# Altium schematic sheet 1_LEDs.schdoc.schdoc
size 309 x 223 mm; Symbol: Sheet-Symbol_A4; Device: Sheet-Symbol_A4; @Project Name: LuxBadge2024; @Page Count: 2; @Update Date: 2024-06-25; @Create Date: 2024-06-16; @Schematic Name: Schematic1; @Page No: 2; @Page Name: LEDs; Company: EasyEDA.com; Reviewed: EasyEDA; Version: V0.1; Page Size: A4; Part Number: JLCPCB-002; Drawn: EasyEDA
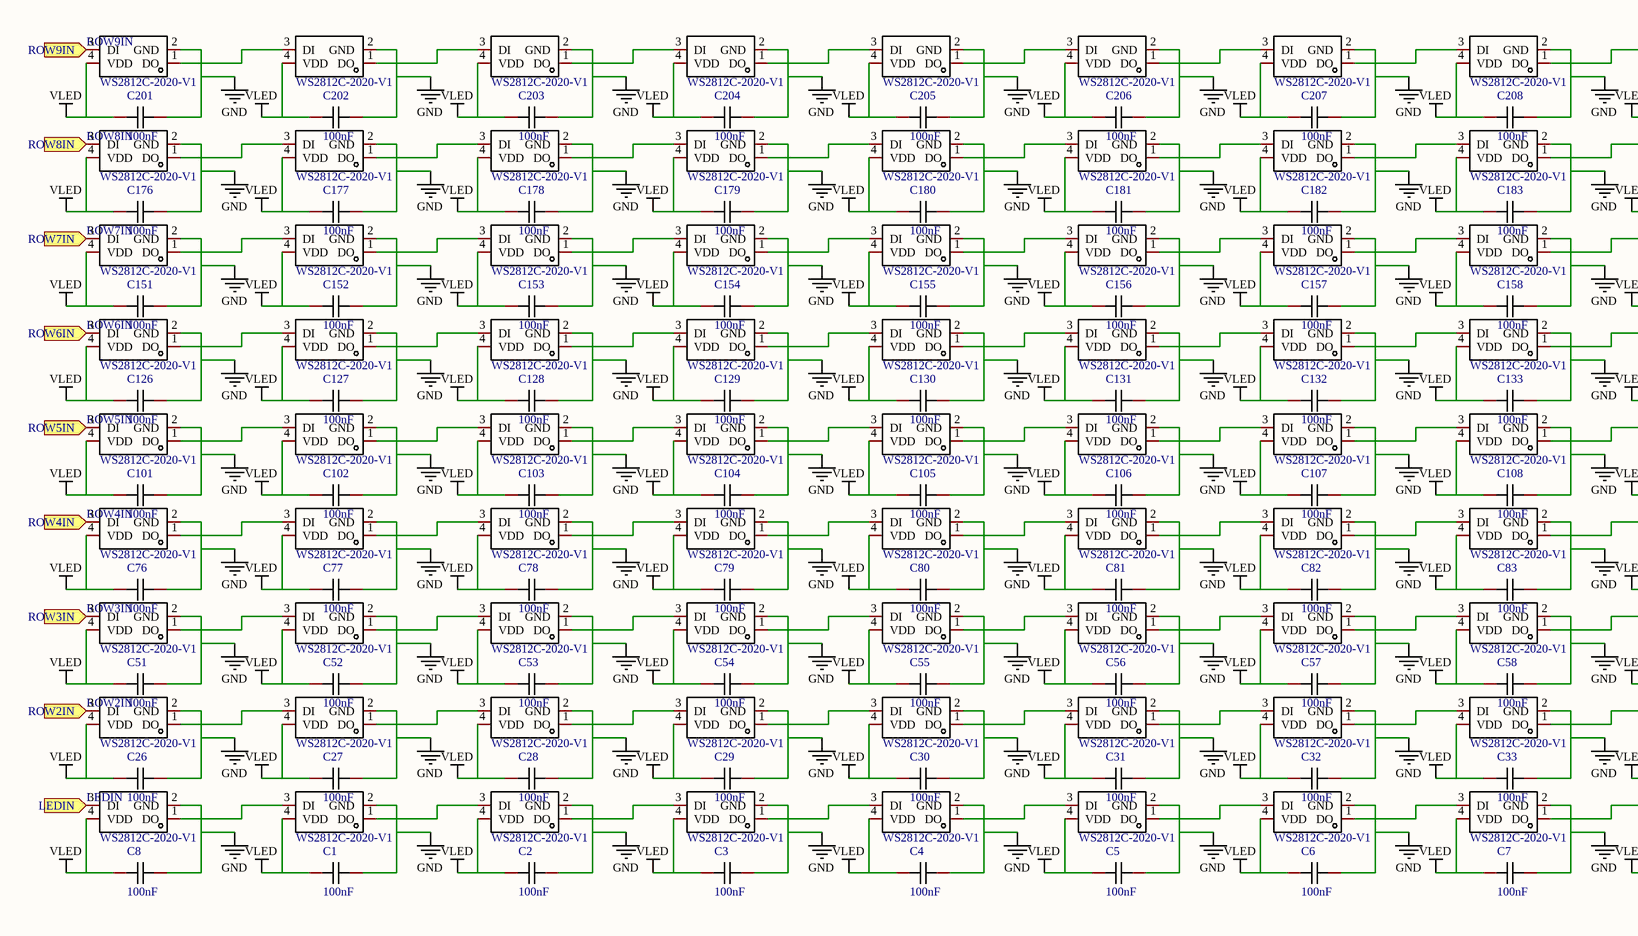
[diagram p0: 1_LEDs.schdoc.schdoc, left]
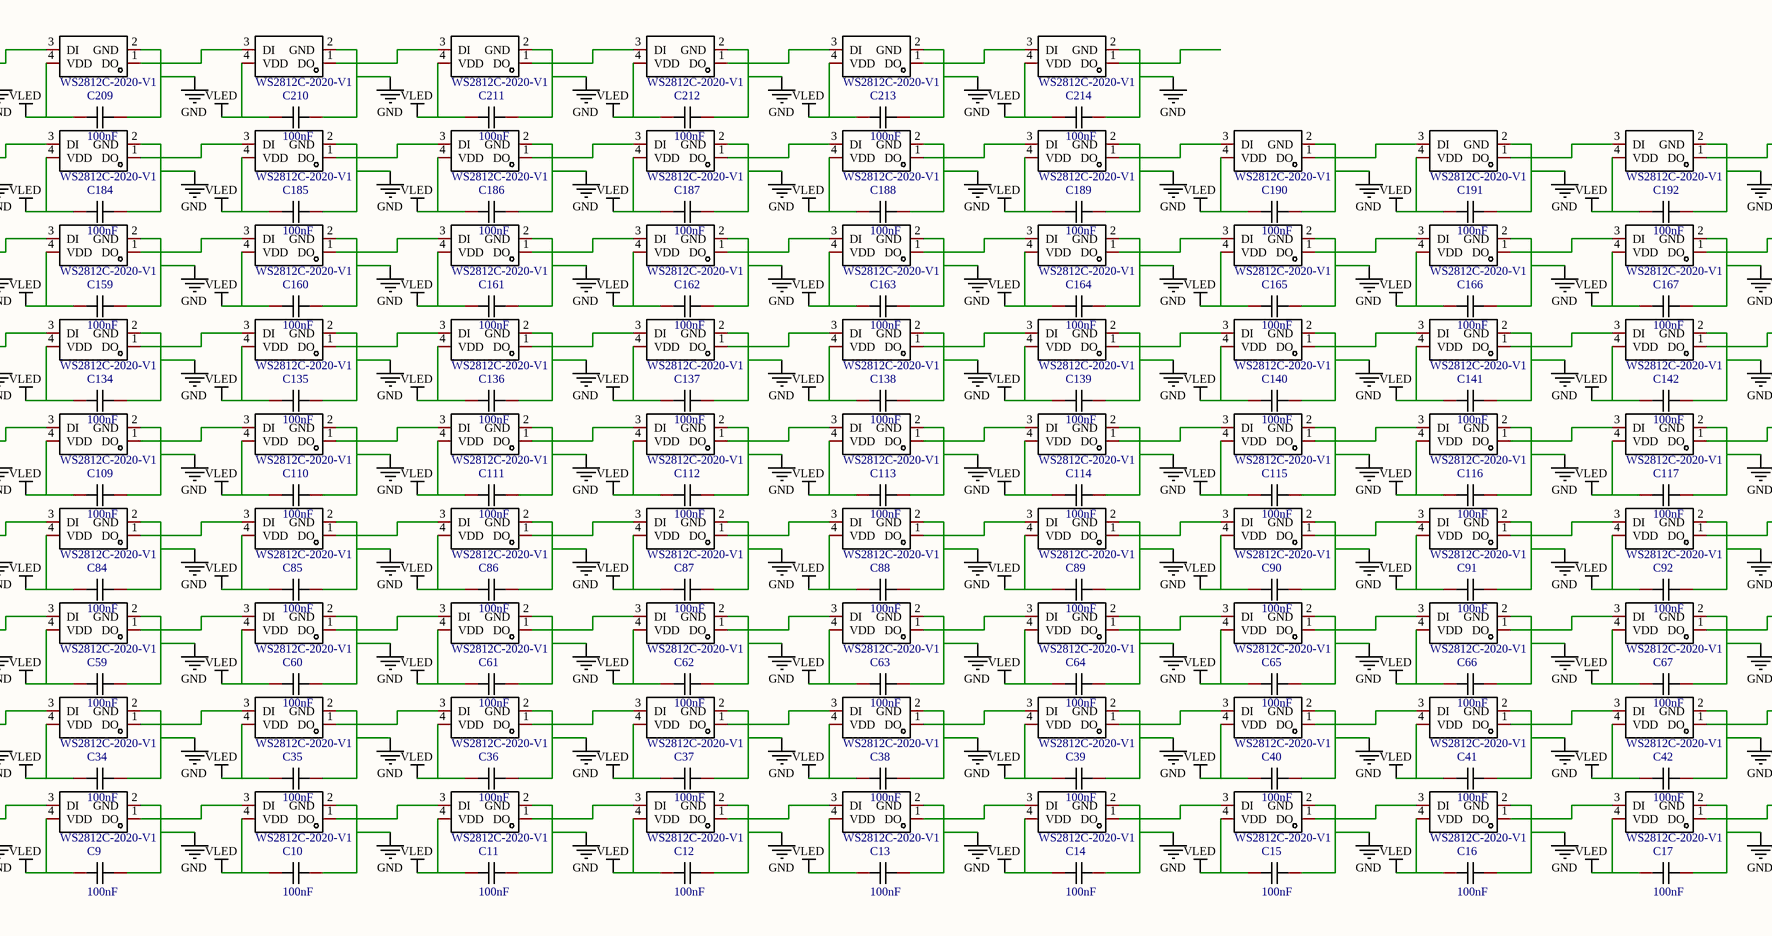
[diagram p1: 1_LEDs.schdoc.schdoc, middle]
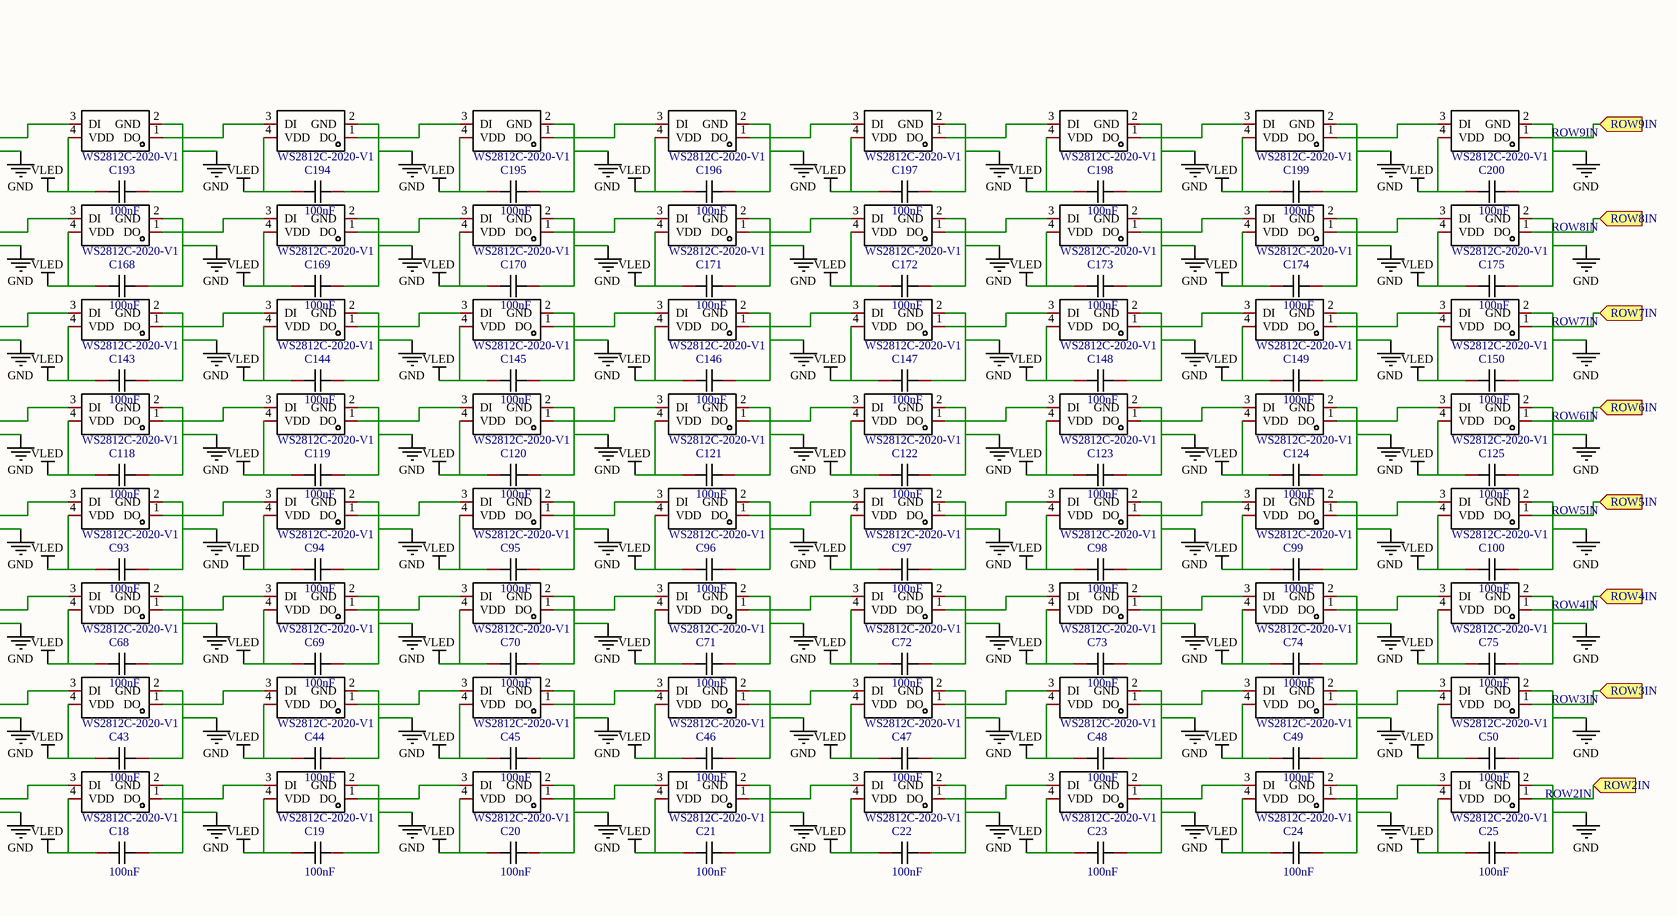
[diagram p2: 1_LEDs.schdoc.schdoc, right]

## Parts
C1  100nF  [C0402]
C2  100nF  [C0402]
C3  100nF  [C0402]
C4  100nF  [C0402]
C5  100nF  [C0402]
C6  100nF  [C0402]
C7  100nF  [C0402]
C8  100nF  [C0402]
C9  100nF  [C0402]
C10  100nF  [C0402]
C11  100nF  [C0402]
C12  100nF  [C0402]
C13  100nF  [C0402]
C14  100nF  [C0402]
C15  100nF  [C0402]
C16  100nF  [C0402]
C17  100nF  [C0402]
C18  100nF  [C0402]
C19  100nF  [C0402]
C20  100nF  [C0402]
C21  100nF  [C0402]
C22  100nF  [C0402]
C23  100nF  [C0402]
C24  100nF  [C0402]
C25  100nF  [C0402]
C26  100nF  [C0402]
C27  100nF  [C0402]
C28  100nF  [C0402]
C29  100nF  [C0402]
C30  100nF  [C0402]
C31  100nF  [C0402]
C32  100nF  [C0402]
C33  100nF  [C0402]
C34  100nF  [C0402]
C35  100nF  [C0402]
C36  100nF  [C0402]
C37  100nF  [C0402]
C38  100nF  [C0402]
C39  100nF  [C0402]
C40  100nF  [C0402]
C41  100nF  [C0402]
C42  100nF  [C0402]
C43  100nF  [C0402]
C44  100nF  [C0402]
C45  100nF  [C0402]
C46  100nF  [C0402]
C47  100nF  [C0402]
C48  100nF  [C0402]
C49  100nF  [C0402]
C50  100nF  [C0402]
C51  100nF  [C0402]
C52  100nF  [C0402]
C53  100nF  [C0402]
C54  100nF  [C0402]
C55  100nF  [C0402]
C56  100nF  [C0402]
C57  100nF  [C0402]
C58  100nF  [C0402]
C59  100nF  [C0402]
C60  100nF  [C0402]
C61  100nF  [C0402]
C62  100nF  [C0402]
C63  100nF  [C0402]
C64  100nF  [C0402]
C65  100nF  [C0402]
C66  100nF  [C0402]
C67  100nF  [C0402]
C68  100nF  [C0402]
C69  100nF  [C0402]
C70  100nF  [C0402]
C71  100nF  [C0402]
C72  100nF  [C0402]
C73  100nF  [C0402]
C74  100nF  [C0402]
C75  100nF  [C0402]
C76  100nF  [C0402]
C77  100nF  [C0402]
C78  100nF  [C0402]
C79  100nF  [C0402]
C80  100nF  [C0402]
C81  100nF  [C0402]
C82  100nF  [C0402]
C83  100nF  [C0402]
C84  100nF  [C0402]
C85  100nF  [C0402]
C86  100nF  [C0402]
C87  100nF  [C0402]
C88  100nF  [C0402]
C89  100nF  [C0402]
C90  100nF  [C0402]
C91  100nF  [C0402]
C92  100nF  [C0402]
C93  100nF  [C0402]
C94  100nF  [C0402]
C95  100nF  [C0402]
C96  100nF  [C0402]
C97  100nF  [C0402]
C98  100nF  [C0402]
C99  100nF  [C0402]
C100  100nF  [C0402]
C101  100nF  [C0402]
C102  100nF  [C0402]
C103  100nF  [C0402]
C104  100nF  [C0402]
C105  100nF  [C0402]
C106  100nF  [C0402]
C107  100nF  [C0402]
C108  100nF  [C0402]
C109  100nF  [C0402]
C110  100nF  [C0402]
C111  100nF  [C0402]
C112  100nF  [C0402]
C113  100nF  [C0402]
C114  100nF  [C0402]
C115  100nF  [C0402]
C116  100nF  [C0402]
C117  100nF  [C0402]
C118  100nF  [C0402]
C119  100nF  [C0402]
C120  100nF  [C0402]
C121  100nF  [C0402]
C122  100nF  [C0402]
C123  100nF  [C0402]
C124  100nF  [C0402]
C125  100nF  [C0402]
C126  100nF  [C0402]
C127  100nF  [C0402]
C128  100nF  [C0402]
C129  100nF  [C0402]
C130  100nF  [C0402]
C131  100nF  [C0402]
C132  100nF  [C0402]
C133  100nF  [C0402]
C134  100nF  [C0402]
C135  100nF  [C0402]
C136  100nF  [C0402]
C137  100nF  [C0402]
C138  100nF  [C0402]
C139  100nF  [C0402]
C140  100nF  [C0402]
C141  100nF  [C0402]
C142  100nF  [C0402]
C143  100nF  [C0402]
C144  100nF  [C0402]
C145  100nF  [C0402]
C146  100nF  [C0402]
C147  100nF  [C0402]
C148  100nF  [C0402]
C149  100nF  [C0402]
C150  100nF  [C0402]
C151  100nF  [C0402]
C152  100nF  [C0402]
C153  100nF  [C0402]
C154  100nF  [C0402]
C155  100nF  [C0402]
C156  100nF  [C0402]
C157  100nF  [C0402]
C158  100nF  [C0402]
C159  100nF  [C0402]
C160  100nF  [C0402]
C161  100nF  [C0402]
C162  100nF  [C0402]
C163  100nF  [C0402]
C164  100nF  [C0402]
C165  100nF  [C0402]
C166  100nF  [C0402]
C167  100nF  [C0402]
C168  100nF  [C0402]
C169  100nF  [C0402]
C170  100nF  [C0402]
C171  100nF  [C0402]
C172  100nF  [C0402]
C173  100nF  [C0402]
C174  100nF  [C0402]
C175  100nF  [C0402]
C176  100nF  [C0402]
C177  100nF  [C0402]
C178  100nF  [C0402]
C179  100nF  [C0402]
C180  100nF  [C0402]
C181  100nF  [C0402]
C182  100nF  [C0402]
C183  100nF  [C0402]
C184  100nF  [C0402]
C185  100nF  [C0402]
C186  100nF  [C0402]
C187  100nF  [C0402]
C188  100nF  [C0402]
C189  100nF  [C0402]
C190  100nF  [C0402]
C191  100nF  [C0402]
C192  100nF  [C0402]
C193  100nF  [C0402]
C194  100nF  [C0402]
C195  100nF  [C0402]
C196  100nF  [C0402]
C197  100nF  [C0402]
C198  100nF  [C0402]
C199  100nF  [C0402]
C200  100nF  [C0402]
C201  100nF  [C0402]
C202  100nF  [C0402]
C203  100nF  [C0402]
C204  100nF  [C0402]
C205  100nF  [C0402]
C206  100nF  [C0402]
C207  100nF  [C0402]
C208  100nF  [C0402]
C209  100nF  [C0402]
C210  100nF  [C0402]
C211  100nF  [C0402]
C212  100nF  [C0402]
C213  100nF  [C0402]
C214  100nF  [C0402]
LED1  WS2812C-2020-V1  [LED-SMD_4P-L2.0-W2.0-TL_WS2812B-2020]
LED2  WS2812C-2020-V1  [LED-SMD_4P-L2.0-W2.0-TL_WS2812B-2020]
LED3  WS2812C-2020-V1  [LED-SMD_4P-L2.0-W2.0-TL_WS2812B-2020]
LED4  WS2812C-2020-V1  [LED-SMD_4P-L2.0-W2.0-TL_WS2812B-2020]
LED5  WS2812C-2020-V1  [LED-SMD_4P-L2.0-W2.0-TL_WS2812B-2020]
LED6  WS2812C-2020-V1  [LED-SMD_4P-L2.0-W2.0-TL_WS2812B-2020]
LED7  WS2812C-2020-V1  [LED-SMD_4P-L2.0-W2.0-TL_WS2812B-2020]
LED8  WS2812C-2020-V1  [LED-SMD_4P-L2.0-W2.0-TL_WS2812B-2020]
LED9  WS2812C-2020-V1  [LED-SMD_4P-L2.0-W2.0-TL_WS2812B-2020]
LED10  WS2812C-2020-V1  [LED-SMD_4P-L2.0-W2.0-TL_WS2812B-2020]
LED11  WS2812C-2020-V1  [LED-SMD_4P-L2.0-W2.0-TL_WS2812B-2020]
LED12  WS2812C-2020-V1  [LED-SMD_4P-L2.0-W2.0-TL_WS2812B-2020]
LED13  WS2812C-2020-V1  [LED-SMD_4P-L2.0-W2.0-TL_WS2812B-2020]
LED14  WS2812C-2020-V1  [LED-SMD_4P-L2.0-W2.0-TL_WS2812B-2020]
LED15  WS2812C-2020-V1  [LED-SMD_4P-L2.0-W2.0-TL_WS2812B-2020]
LED16  WS2812C-2020-V1  [LED-SMD_4P-L2.0-W2.0-TL_WS2812B-2020]
LED17  WS2812C-2020-V1  [LED-SMD_4P-L2.0-W2.0-TL_WS2812B-2020]
LED18  WS2812C-2020-V1  [LED-SMD_4P-L2.0-W2.0-TL_WS2812B-2020]
LED19  WS2812C-2020-V1  [LED-SMD_4P-L2.0-W2.0-TL_WS2812B-2020]
LED20  WS2812C-2020-V1  [LED-SMD_4P-L2.0-W2.0-TL_WS2812B-2020]
LED21  WS2812C-2020-V1  [LED-SMD_4P-L2.0-W2.0-TL_WS2812B-2020]
LED22  WS2812C-2020-V1  [LED-SMD_4P-L2.0-W2.0-TL_WS2812B-2020]
LED23  WS2812C-2020-V1  [LED-SMD_4P-L2.0-W2.0-TL_WS2812B-2020]
LED24  WS2812C-2020-V1  [LED-SMD_4P-L2.0-W2.0-TL_WS2812B-2020]
LED25  WS2812C-2020-V1  [LED-SMD_4P-L2.0-W2.0-TL_WS2812B-2020]
LED26  WS2812C-2020-V1  [LED-SMD_4P-L2.0-W2.0-TL_WS2812B-2020]
LED27  WS2812C-2020-V1  [LED-SMD_4P-L2.0-W2.0-TL_WS2812B-2020]
LED28  WS2812C-2020-V1  [LED-SMD_4P-L2.0-W2.0-TL_WS2812B-2020]
LED29  WS2812C-2020-V1  [LED-SMD_4P-L2.0-W2.0-TL_WS2812B-2020]
LED30  WS2812C-2020-V1  [LED-SMD_4P-L2.0-W2.0-TL_WS2812B-2020]
LED31  WS2812C-2020-V1  [LED-SMD_4P-L2.0-W2.0-TL_WS2812B-2020]
LED32  WS2812C-2020-V1  [LED-SMD_4P-L2.0-W2.0-TL_WS2812B-2020]
LED33  WS2812C-2020-V1  [LED-SMD_4P-L2.0-W2.0-TL_WS2812B-2020]
LED34  WS2812C-2020-V1  [LED-SMD_4P-L2.0-W2.0-TL_WS2812B-2020]
LED35  WS2812C-2020-V1  [LED-SMD_4P-L2.0-W2.0-TL_WS2812B-2020]
LED36  WS2812C-2020-V1  [LED-SMD_4P-L2.0-W2.0-TL_WS2812B-2020]
LED37  WS2812C-2020-V1  [LED-SMD_4P-L2.0-W2.0-TL_WS2812B-2020]
LED38  WS2812C-2020-V1  [LED-SMD_4P-L2.0-W2.0-TL_WS2812B-2020]
LED39  WS2812C-2020-V1  [LED-SMD_4P-L2.0-W2.0-TL_WS2812B-2020]
LED40  WS2812C-2020-V1  [LED-SMD_4P-L2.0-W2.0-TL_WS2812B-2020]
LED41  WS2812C-2020-V1  [LED-SMD_4P-L2.0-W2.0-TL_WS2812B-2020]
LED42  WS2812C-2020-V1  [LED-SMD_4P-L2.0-W2.0-TL_WS2812B-2020]
LED43  WS2812C-2020-V1  [LED-SMD_4P-L2.0-W2.0-TL_WS2812B-2020]
LED44  WS2812C-2020-V1  [LED-SMD_4P-L2.0-W2.0-TL_WS2812B-2020]
LED45  WS2812C-2020-V1  [LED-SMD_4P-L2.0-W2.0-TL_WS2812B-2020]
LED46  WS2812C-2020-V1  [LED-SMD_4P-L2.0-W2.0-TL_WS2812B-2020]
LED47  WS2812C-2020-V1  [LED-SMD_4P-L2.0-W2.0-TL_WS2812B-2020]
LED48  WS2812C-2020-V1  [LED-SMD_4P-L2.0-W2.0-TL_WS2812B-2020]
LED49  WS2812C-2020-V1  [LED-SMD_4P-L2.0-W2.0-TL_WS2812B-2020]
LED50  WS2812C-2020-V1  [LED-SMD_4P-L2.0-W2.0-TL_WS2812B-2020]
LED51  WS2812C-2020-V1  [LED-SMD_4P-L2.0-W2.0-TL_WS2812B-2020]
LED52  WS2812C-2020-V1  [LED-SMD_4P-L2.0-W2.0-TL_WS2812B-2020]
LED53  WS2812C-2020-V1  [LED-SMD_4P-L2.0-W2.0-TL_WS2812B-2020]
LED54  WS2812C-2020-V1  [LED-SMD_4P-L2.0-W2.0-TL_WS2812B-2020]
LED55  WS2812C-2020-V1  [LED-SMD_4P-L2.0-W2.0-TL_WS2812B-2020]
LED56  WS2812C-2020-V1  [LED-SMD_4P-L2.0-W2.0-TL_WS2812B-2020]
LED57  WS2812C-2020-V1  [LED-SMD_4P-L2.0-W2.0-TL_WS2812B-2020]
LED58  WS2812C-2020-V1  [LED-SMD_4P-L2.0-W2.0-TL_WS2812B-2020]
LED59  WS2812C-2020-V1  [LED-SMD_4P-L2.0-W2.0-TL_WS2812B-2020]
LED60  WS2812C-2020-V1  [LED-SMD_4P-L2.0-W2.0-TL_WS2812B-2020]
LED61  WS2812C-2020-V1  [LED-SMD_4P-L2.0-W2.0-TL_WS2812B-2020]
LED62  WS2812C-2020-V1  [LED-SMD_4P-L2.0-W2.0-TL_WS2812B-2020]
LED63  WS2812C-2020-V1  [LED-SMD_4P-L2.0-W2.0-TL_WS2812B-2020]
LED64  WS2812C-2020-V1  [LED-SMD_4P-L2.0-W2.0-TL_WS2812B-2020]
LED65  WS2812C-2020-V1  [LED-SMD_4P-L2.0-W2.0-TL_WS2812B-2020]
LED66  WS2812C-2020-V1  [LED-SMD_4P-L2.0-W2.0-TL_WS2812B-2020]
LED67  WS2812C-2020-V1  [LED-SMD_4P-L2.0-W2.0-TL_WS2812B-2020]
LED68  WS2812C-2020-V1  [LED-SMD_4P-L2.0-W2.0-TL_WS2812B-2020]
LED69  WS2812C-2020-V1  [LED-SMD_4P-L2.0-W2.0-TL_WS2812B-2020]
LED70  WS2812C-2020-V1  [LED-SMD_4P-L2.0-W2.0-TL_WS2812B-2020]
LED71  WS2812C-2020-V1  [LED-SMD_4P-L2.0-W2.0-TL_WS2812B-2020]
LED72  WS2812C-2020-V1  [LED-SMD_4P-L2.0-W2.0-TL_WS2812B-2020]
LED73  WS2812C-2020-V1  [LED-SMD_4P-L2.0-W2.0-TL_WS2812B-2020]
LED74  WS2812C-2020-V1  [LED-SMD_4P-L2.0-W2.0-TL_WS2812B-2020]
LED75  WS2812C-2020-V1  [LED-SMD_4P-L2.0-W2.0-TL_WS2812B-2020]
LED76  WS2812C-2020-V1  [LED-SMD_4P-L2.0-W2.0-TL_WS2812B-2020]
LED77  WS2812C-2020-V1  [LED-SMD_4P-L2.0-W2.0-TL_WS2812B-2020]
LED78  WS2812C-2020-V1  [LED-SMD_4P-L2.0-W2.0-TL_WS2812B-2020]
LED79  WS2812C-2020-V1  [LED-SMD_4P-L2.0-W2.0-TL_WS2812B-2020]
LED80  WS2812C-2020-V1  [LED-SMD_4P-L2.0-W2.0-TL_WS2812B-2020]
LED81  WS2812C-2020-V1  [LED-SMD_4P-L2.0-W2.0-TL_WS2812B-2020]
LED82  WS2812C-2020-V1  [LED-SMD_4P-L2.0-W2.0-TL_WS2812B-2020]
LED83  WS2812C-2020-V1  [LED-SMD_4P-L2.0-W2.0-TL_WS2812B-2020]
LED84  WS2812C-2020-V1  [LED-SMD_4P-L2.0-W2.0-TL_WS2812B-2020]
LED85  WS2812C-2020-V1  [LED-SMD_4P-L2.0-W2.0-TL_WS2812B-2020]
LED86  WS2812C-2020-V1  [LED-SMD_4P-L2.0-W2.0-TL_WS2812B-2020]
LED87  WS2812C-2020-V1  [LED-SMD_4P-L2.0-W2.0-TL_WS2812B-2020]
LED88  WS2812C-2020-V1  [LED-SMD_4P-L2.0-W2.0-TL_WS2812B-2020]
LED89  WS2812C-2020-V1  [LED-SMD_4P-L2.0-W2.0-TL_WS2812B-2020]
LED90  WS2812C-2020-V1  [LED-SMD_4P-L2.0-W2.0-TL_WS2812B-2020]
LED91  WS2812C-2020-V1  [LED-SMD_4P-L2.0-W2.0-TL_WS2812B-2020]
LED92  WS2812C-2020-V1  [LED-SMD_4P-L2.0-W2.0-TL_WS2812B-2020]
LED93  WS2812C-2020-V1  [LED-SMD_4P-L2.0-W2.0-TL_WS2812B-2020]
LED94  WS2812C-2020-V1  [LED-SMD_4P-L2.0-W2.0-TL_WS2812B-2020]
LED95  WS2812C-2020-V1  [LED-SMD_4P-L2.0-W2.0-TL_WS2812B-2020]
LED96  WS2812C-2020-V1  [LED-SMD_4P-L2.0-W2.0-TL_WS2812B-2020]
LED97  WS2812C-2020-V1  [LED-SMD_4P-L2.0-W2.0-TL_WS2812B-2020]
LED98  WS2812C-2020-V1  [LED-SMD_4P-L2.0-W2.0-TL_WS2812B-2020]
LED99  WS2812C-2020-V1  [LED-SMD_4P-L2.0-W2.0-TL_WS2812B-2020]
LED100  WS2812C-2020-V1  [LED-SMD_4P-L2.0-W2.0-TL_WS2812B-2020]
LED101  WS2812C-2020-V1  [LED-SMD_4P-L2.0-W2.0-TL_WS2812B-2020]
LED102  WS2812C-2020-V1  [LED-SMD_4P-L2.0-W2.0-TL_WS2812B-2020]
LED103  WS2812C-2020-V1  [LED-SMD_4P-L2.0-W2.0-TL_WS2812B-2020]
LED104  WS2812C-2020-V1  [LED-SMD_4P-L2.0-W2.0-TL_WS2812B-2020]
LED105  WS2812C-2020-V1  [LED-SMD_4P-L2.0-W2.0-TL_WS2812B-2020]
LED106  WS2812C-2020-V1  [LED-SMD_4P-L2.0-W2.0-TL_WS2812B-2020]
LED107  WS2812C-2020-V1  [LED-SMD_4P-L2.0-W2.0-TL_WS2812B-2020]
LED108  WS2812C-2020-V1  [LED-SMD_4P-L2.0-W2.0-TL_WS2812B-2020]
LED109  WS2812C-2020-V1  [LED-SMD_4P-L2.0-W2.0-TL_WS2812B-2020]
LED110  WS2812C-2020-V1  [LED-SMD_4P-L2.0-W2.0-TL_WS2812B-2020]
LED111  WS2812C-2020-V1  [LED-SMD_4P-L2.0-W2.0-TL_WS2812B-2020]
LED112  WS2812C-2020-V1  [LED-SMD_4P-L2.0-W2.0-TL_WS2812B-2020]
LED113  WS2812C-2020-V1  [LED-SMD_4P-L2.0-W2.0-TL_WS2812B-2020]
LED114  WS2812C-2020-V1  [LED-SMD_4P-L2.0-W2.0-TL_WS2812B-2020]
LED115  WS2812C-2020-V1  [LED-SMD_4P-L2.0-W2.0-TL_WS2812B-2020]
LED116  WS2812C-2020-V1  [LED-SMD_4P-L2.0-W2.0-TL_WS2812B-2020]
LED117  WS2812C-2020-V1  [LED-SMD_4P-L2.0-W2.0-TL_WS2812B-2020]
LED118  WS2812C-2020-V1  [LED-SMD_4P-L2.0-W2.0-TL_WS2812B-2020]
LED119  WS2812C-2020-V1  [LED-SMD_4P-L2.0-W2.0-TL_WS2812B-2020]
LED120  WS2812C-2020-V1  [LED-SMD_4P-L2.0-W2.0-TL_WS2812B-2020]
LED121  WS2812C-2020-V1  [LED-SMD_4P-L2.0-W2.0-TL_WS2812B-2020]
LED122  WS2812C-2020-V1  [LED-SMD_4P-L2.0-W2.0-TL_WS2812B-2020]
LED123  WS2812C-2020-V1  [LED-SMD_4P-L2.0-W2.0-TL_WS2812B-2020]
LED124  WS2812C-2020-V1  [LED-SMD_4P-L2.0-W2.0-TL_WS2812B-2020]
LED125  WS2812C-2020-V1  [LED-SMD_4P-L2.0-W2.0-TL_WS2812B-2020]
LED126  WS2812C-2020-V1  [LED-SMD_4P-L2.0-W2.0-TL_WS2812B-2020]
LED127  WS2812C-2020-V1  [LED-SMD_4P-L2.0-W2.0-TL_WS2812B-2020]
LED128  WS2812C-2020-V1  [LED-SMD_4P-L2.0-W2.0-TL_WS2812B-2020]
LED129  WS2812C-2020-V1  [LED-SMD_4P-L2.0-W2.0-TL_WS2812B-2020]
LED130  WS2812C-2020-V1  [LED-SMD_4P-L2.0-W2.0-TL_WS2812B-2020]
LED131  WS2812C-2020-V1  [LED-SMD_4P-L2.0-W2.0-TL_WS2812B-2020]
LED132  WS2812C-2020-V1  [LED-SMD_4P-L2.0-W2.0-TL_WS2812B-2020]
LED133  WS2812C-2020-V1  [LED-SMD_4P-L2.0-W2.0-TL_WS2812B-2020]
LED134  WS2812C-2020-V1  [LED-SMD_4P-L2.0-W2.0-TL_WS2812B-2020]
LED135  WS2812C-2020-V1  [LED-SMD_4P-L2.0-W2.0-TL_WS2812B-2020]
LED136  WS2812C-2020-V1  [LED-SMD_4P-L2.0-W2.0-TL_WS2812B-2020]
LED137  WS2812C-2020-V1  [LED-SMD_4P-L2.0-W2.0-TL_WS2812B-2020]
LED138  WS2812C-2020-V1  [LED-SMD_4P-L2.0-W2.0-TL_WS2812B-2020]
LED139  WS2812C-2020-V1  [LED-SMD_4P-L2.0-W2.0-TL_WS2812B-2020]
LED140  WS2812C-2020-V1  [LED-SMD_4P-L2.0-W2.0-TL_WS2812B-2020]
LED141  WS2812C-2020-V1  [LED-SMD_4P-L2.0-W2.0-TL_WS2812B-2020]
LED142  WS2812C-2020-V1  [LED-SMD_4P-L2.0-W2.0-TL_WS2812B-2020]
LED143  WS2812C-2020-V1  [LED-SMD_4P-L2.0-W2.0-TL_WS2812B-2020]
LED144  WS2812C-2020-V1  [LED-SMD_4P-L2.0-W2.0-TL_WS2812B-2020]
LED145  WS2812C-2020-V1  [LED-SMD_4P-L2.0-W2.0-TL_WS2812B-2020]
LED146  WS2812C-2020-V1  [LED-SMD_4P-L2.0-W2.0-TL_WS2812B-2020]
LED147  WS2812C-2020-V1  [LED-SMD_4P-L2.0-W2.0-TL_WS2812B-2020]
LED148  WS2812C-2020-V1  [LED-SMD_4P-L2.0-W2.0-TL_WS2812B-2020]
LED149  WS2812C-2020-V1  [LED-SMD_4P-L2.0-W2.0-TL_WS2812B-2020]
LED150  WS2812C-2020-V1  [LED-SMD_4P-L2.0-W2.0-TL_WS2812B-2020]
LED151  WS2812C-2020-V1  [LED-SMD_4P-L2.0-W2.0-TL_WS2812B-2020]
LED152  WS2812C-2020-V1  [LED-SMD_4P-L2.0-W2.0-TL_WS2812B-2020]
LED153  WS2812C-2020-V1  [LED-SMD_4P-L2.0-W2.0-TL_WS2812B-2020]
LED154  WS2812C-2020-V1  [LED-SMD_4P-L2.0-W2.0-TL_WS2812B-2020]
LED155  WS2812C-2020-V1  [LED-SMD_4P-L2.0-W2.0-TL_WS2812B-2020]
LED156  WS2812C-2020-V1  [LED-SMD_4P-L2.0-W2.0-TL_WS2812B-2020]
LED157  WS2812C-2020-V1  [LED-SMD_4P-L2.0-W2.0-TL_WS2812B-2020]
LED158  WS2812C-2020-V1  [LED-SMD_4P-L2.0-W2.0-TL_WS2812B-2020]
LED159  WS2812C-2020-V1  [LED-SMD_4P-L2.0-W2.0-TL_WS2812B-2020]
LED160  WS2812C-2020-V1  [LED-SMD_4P-L2.0-W2.0-TL_WS2812B-2020]
LED161  WS2812C-2020-V1  [LED-SMD_4P-L2.0-W2.0-TL_WS2812B-2020]
LED162  WS2812C-2020-V1  [LED-SMD_4P-L2.0-W2.0-TL_WS2812B-2020]
LED163  WS2812C-2020-V1  [LED-SMD_4P-L2.0-W2.0-TL_WS2812B-2020]
LED164  WS2812C-2020-V1  [LED-SMD_4P-L2.0-W2.0-TL_WS2812B-2020]
LED165  WS2812C-2020-V1  [LED-SMD_4P-L2.0-W2.0-TL_WS2812B-2020]
LED166  WS2812C-2020-V1  [LED-SMD_4P-L2.0-W2.0-TL_WS2812B-2020]
LED167  WS2812C-2020-V1  [LED-SMD_4P-L2.0-W2.0-TL_WS2812B-2020]
LED168  WS2812C-2020-V1  [LED-SMD_4P-L2.0-W2.0-TL_WS2812B-2020]
LED169  WS2812C-2020-V1  [LED-SMD_4P-L2.0-W2.0-TL_WS2812B-2020]
LED170  WS2812C-2020-V1  [LED-SMD_4P-L2.0-W2.0-TL_WS2812B-2020]
LED171  WS2812C-2020-V1  [LED-SMD_4P-L2.0-W2.0-TL_WS2812B-2020]
LED172  WS2812C-2020-V1  [LED-SMD_4P-L2.0-W2.0-TL_WS2812B-2020]
LED173  WS2812C-2020-V1  [LED-SMD_4P-L2.0-W2.0-TL_WS2812B-2020]
LED174  WS2812C-2020-V1  [LED-SMD_4P-L2.0-W2.0-TL_WS2812B-2020]
LED175  WS2812C-2020-V1  [LED-SMD_4P-L2.0-W2.0-TL_WS2812B-2020]
LED176  WS2812C-2020-V1  [LED-SMD_4P-L2.0-W2.0-TL_WS2812B-2020]
LED177  WS2812C-2020-V1  [LED-SMD_4P-L2.0-W2.0-TL_WS2812B-2020]
LED178  WS2812C-2020-V1  [LED-SMD_4P-L2.0-W2.0-TL_WS2812B-2020]
LED179  WS2812C-2020-V1  [LED-SMD_4P-L2.0-W2.0-TL_WS2812B-2020]
LED180  WS2812C-2020-V1  [LED-SMD_4P-L2.0-W2.0-TL_WS2812B-2020]
LED181  WS2812C-2020-V1  [LED-SMD_4P-L2.0-W2.0-TL_WS2812B-2020]
LED182  WS2812C-2020-V1  [LED-SMD_4P-L2.0-W2.0-TL_WS2812B-2020]
LED183  WS2812C-2020-V1  [LED-SMD_4P-L2.0-W2.0-TL_WS2812B-2020]
LED184  WS2812C-2020-V1  [LED-SMD_4P-L2.0-W2.0-TL_WS2812B-2020]
LED185  WS2812C-2020-V1  [LED-SMD_4P-L2.0-W2.0-TL_WS2812B-2020]
LED186  WS2812C-2020-V1  [LED-SMD_4P-L2.0-W2.0-TL_WS2812B-2020]
LED187  WS2812C-2020-V1  [LED-SMD_4P-L2.0-W2.0-TL_WS2812B-2020]
LED188  WS2812C-2020-V1  [LED-SMD_4P-L2.0-W2.0-TL_WS2812B-2020]
LED189  WS2812C-2020-V1  [LED-SMD_4P-L2.0-W2.0-TL_WS2812B-2020]
LED190  WS2812C-2020-V1  [LED-SMD_4P-L2.0-W2.0-TL_WS2812B-2020]
LED191  WS2812C-2020-V1  [LED-SMD_4P-L2.0-W2.0-TL_WS2812B-2020]
LED192  WS2812C-2020-V1  [LED-SMD_4P-L2.0-W2.0-TL_WS2812B-2020]
LED193  WS2812C-2020-V1  [LED-SMD_4P-L2.0-W2.0-TL_WS2812B-2020]
LED194  WS2812C-2020-V1  [LED-SMD_4P-L2.0-W2.0-TL_WS2812B-2020]
LED195  WS2812C-2020-V1  [LED-SMD_4P-L2.0-W2.0-TL_WS2812B-2020]
LED196  WS2812C-2020-V1  [LED-SMD_4P-L2.0-W2.0-TL_WS2812B-2020]
LED197  WS2812C-2020-V1  [LED-SMD_4P-L2.0-W2.0-TL_WS2812B-2020]
LED198  WS2812C-2020-V1  [LED-SMD_4P-L2.0-W2.0-TL_WS2812B-2020]
LED199  WS2812C-2020-V1  [LED-SMD_4P-L2.0-W2.0-TL_WS2812B-2020]
LED200  WS2812C-2020-V1  [LED-SMD_4P-L2.0-W2.0-TL_WS2812B-2020]
LED201  WS2812C-2020-V1  [LED-SMD_4P-L2.0-W2.0-TL_WS2812B-2020]
LED202  WS2812C-2020-V1  [LED-SMD_4P-L2.0-W2.0-TL_WS2812B-2020]
LED203  WS2812C-2020-V1  [LED-SMD_4P-L2.0-W2.0-TL_WS2812B-2020]
LED204  WS2812C-2020-V1  [LED-SMD_4P-L2.0-W2.0-TL_WS2812B-2020]
LED205  WS2812C-2020-V1  [LED-SMD_4P-L2.0-W2.0-TL_WS2812B-2020]
LED206  WS2812C-2020-V1  [LED-SMD_4P-L2.0-W2.0-TL_WS2812B-2020]
LED207  WS2812C-2020-V1  [LED-SMD_4P-L2.0-W2.0-TL_WS2812B-2020]
LED208  WS2812C-2020-V1  [LED-SMD_4P-L2.0-W2.0-TL_WS2812B-2020]
LED209  WS2812C-2020-V1  [LED-SMD_4P-L2.0-W2.0-TL_WS2812B-2020]
LED210  WS2812C-2020-V1  [LED-SMD_4P-L2.0-W2.0-TL_WS2812B-2020]
LED211  WS2812C-2020-V1  [LED-SMD_4P-L2.0-W2.0-TL_WS2812B-2020]
LED212  WS2812C-2020-V1  [LED-SMD_4P-L2.0-W2.0-TL_WS2812B-2020]
LED213  WS2812C-2020-V1  [LED-SMD_4P-L2.0-W2.0-TL_WS2812B-2020]
LED214  WS2812C-2020-V1  [LED-SMD_4P-L2.0-W2.0-TL_WS2812B-2020]

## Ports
LEDIN (in), ROW2IN (in), ROW3IN (in), ROW4IN (in), ROW5IN (in), ROW6IN (in), ROW7IN (in), ROW8IN (in), ROW9IN (in)

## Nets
GND: C1.1 C2.1 C3.1 C4.1 C5.1 C6.1 C7.1 C8.1 C9.1 C10.1 C11.1 C12.1 C13.1 C14.1 C15.1 C16.1 C17.1 C18.1 C19.1 C20.1 C21.1 C22.1 C23.1 C24.1 C25.1 C26.1 C27.1 C28.1 C29.1 C30.1 C31.1 C32.1 C33.1 C34.1 C35.1 C36.1 C37.1 C38.1 C39.1 C40.1 C41.1 C42.1 C43.1 C44.1 C45.1 C46.1 C47.1 C48.1 C49.1 C50.1 C51.1 C52.1 C53.1 C54.1 C55.1 C56.1 C57.1 C58.1 C59.1 C60.1 C61.1 C62.1 C63.1 C64.1 C65.1 C66.1 C67.1 C68.1 C69.1 C70.1 C71.1 C72.1 C73.1 C74.1 C75.1 C76.1 C77.1 C78.1 C79.1 C80.1 C81.1 C82.1 C83.1 C84.1 C85.1 C86.1 C87.1 C88.1 C89.1 C90.1 C91.1 C92.1 C93.1 C94.1 C95.1 C96.1 C97.1 C98.1 C99.1 C100.1 C101.1 C102.1 C103.1 C104.1 C105.1 C106.1 C107.1 C108.1 C109.1 C110.1 C111.1 C112.1 C113.1 C114.1 C115.1 C116.1 C117.1 C118.1 C119.1 C120.1 C121.1 C122.1 C123.1 C124.1 C125.1 C126.1 C127.1 C128.1 C129.1 C130.1 C131.1 C132.1 C133.1 C134.1 C135.1 C136.1 C137.1 C138.1 C139.1 C140.1 C141.1 C142.1 C143.1 C144.1 C145.1 C146.1 C147.1 C148.1 C149.1 C150.1 C151.1 C152.1 C153.1 C154.1 C155.1 C156.1 C157.1 C158.1 C159.1 C160.1 C161.1 C162.1 C163.1 C164.1 C165.1 C166.1 C167.1 C168.1 C169.1 C170.1 C171.1 C172.1 C173.1 C174.1 C175.1 C176.1 C177.1 C178.1 C179.1 C180.1 C181.1 C182.1 C183.1 C184.1 C185.1 C186.1 C187.1 C188.1 C189.1 C190.1 C191.1 C192.1 C193.1 C194.1 C195.1 C196.1 C197.1 C198.1 C199.1 C200.1 C201.1 C202.1 C203.1 C204.1 C205.1 C206.1 C207.1 C208.1 C209.1 C210.1 C211.1 C212.1 C213.1 C214.1 LED1.2(GND) LED2.2(GND) LED3.2(GND) LED4.2(GND) LED5.2(GND) LED6.2(GND) LED7.2(GND) LED8.2(GND) LED9.2(GND) LED10.2(GND) LED11.2(GND) LED12.2(GND) LED13.2(GND) LED14.2(GND) LED15.2(GND) LED16.2(GND) LED17.2(GND) LED18.2(GND) LED19.2(GND) LED20.2(GND) LED21.2(GND) LED22.2(GND) LED23.2(GND) LED24.2(GND) LED25.2(GND) LED26.2(GND) LED27.2(GND) LED28.2(GND) LED29.2(GND) LED30.2(GND) LED31.2(GND) LED32.2(GND) LED33.2(GND) LED34.2(GND) LED35.2(GND) LED36.2(GND) LED37.2(GND) LED38.2(GND) LED39.2(GND) LED40.2(GND) LED41.2(GND) LED42.2(GND) LED43.2(GND) LED44.2(GND) LED45.2(GND) LED46.2(GND) LED47.2(GND) LED48.2(GND) LED49.2(GND) LED50.2(GND) LED51.2(GND) LED52.2(GND) LED53.2(GND) LED54.2(GND) LED55.2(GND) LED56.2(GND) LED57.2(GND) LED58.2(GND) LED59.2(GND) LED60.2(GND) LED61.2(GND) LED62.2(GND) LED63.2(GND) LED64.2(GND) LED65.2(GND) LED66.2(GND) LED67.2(GND) LED68.2(GND) LED69.2(GND) LED70.2(GND) LED71.2(GND) LED72.2(GND) LED73.2(GND) LED74.2(GND) LED75.2(GND) LED76.2(GND) LED77.2(GND) LED78.2(GND) LED79.2(GND) LED80.2(GND) LED81.2(GND) LED82.2(GND) LED83.2(GND) LED84.2(GND) LED85.2(GND) LED86.2(GND) LED87.2(GND) LED88.2(GND) LED89.2(GND) LED90.2(GND) LED91.2(GND) LED92.2(GND) LED93.2(GND) LED94.2(GND) LED95.2(GND) LED96.2(GND) LED97.2(GND) LED98.2(GND) LED99.2(GND) LED100.2(GND) LED101.2(GND) LED102.2(GND) LED103.2(GND) LED104.2(GND) LED105.2(GND) LED106.2(GND) LED107.2(GND) LED108.2(GND) LED109.2(GND) LED110.2(GND) LED111.2(GND) LED112.2(GND) LED113.2(GND) LED114.2(GND) LED115.2(GND) LED116.2(GND) LED117.2(GND) LED118.2(GND) LED119.2(GND) LED120.2(GND) LED121.2(GND) LED122.2(GND) LED123.2(GND) LED124.2(GND) LED125.2(GND) LED126.2(GND) LED127.2(GND) LED128.2(GND) LED129.2(GND) LED130.2(GND) LED131.2(GND) LED132.2(GND) LED133.2(GND) LED134.2(GND) LED135.2(GND) LED136.2(GND) LED137.2(GND) LED138.2(GND) LED139.2(GND) LED140.2(GND) LED141.2(GND) LED142.2(GND) LED143.2(GND) LED144.2(GND) LED145.2(GND) LED146.2(GND) LED147.2(GND) LED148.2(GND) LED149.2(GND) LED150.2(GND) LED151.2(GND) LED152.2(GND) LED153.2(GND) LED154.2(GND) LED155.2(GND) LED156.2(GND) LED157.2(GND) LED158.2(GND) LED159.2(GND) LED160.2(GND) LED161.2(GND) LED162.2(GND) LED163.2(GND) LED164.2(GND) LED165.2(GND) LED166.2(GND) LED167.2(GND) LED168.2(GND) LED169.2(GND) LED170.2(GND) LED171.2(GND) LED172.2(GND) LED173.2(GND) LED174.2(GND) LED175.2(GND) LED176.2(GND) LED177.2(GND) LED178.2(GND) LED179.2(GND) LED180.2(GND) LED181.2(GND) LED182.2(GND) LED183.2(GND) LED184.2(GND) LED185.2(GND) LED186.2(GND) LED187.2(GND) LED188.2(GND) LED189.2(GND) LED190.2(GND) LED191.2(GND) LED192.2(GND) LED193.2(GND) LED194.2(GND) LED195.2(GND) LED196.2(GND) LED197.2(GND) LED198.2(GND) LED199.2(GND) LED200.2(GND) LED201.2(GND) LED202.2(GND) LED203.2(GND) LED204.2(GND) LED205.2(GND) LED206.2(GND) LED207.2(GND) LED208.2(GND) LED209.2(GND) LED210.2(GND) LED211.2(GND) LED212.2(GND) LED213.2(GND) LED214.2(GND)
VLED: C1.2 C2.2 C3.2 C4.2 C5.2 C6.2 C7.2 C8.2 C9.2 C10.2 C11.2 C12.2 C13.2 C14.2 C15.2 C16.2 C17.2 C18.2 C19.2 C20.2 C21.2 C22.2 C23.2 C24.2 C25.2 C26.2 C27.2 C28.2 C29.2 C30.2 C31.2 C32.2 C33.2 C34.2 C35.2 C36.2 C37.2 C38.2 C39.2 C40.2 C41.2 C42.2 C43.2 C44.2 C45.2 C46.2 C47.2 C48.2 C49.2 C50.2 C51.2 C52.2 C53.2 C54.2 C55.2 C56.2 C57.2 C58.2 C59.2 C60.2 C61.2 C62.2 C63.2 C64.2 C65.2 C66.2 C67.2 C68.2 C69.2 C70.2 C71.2 C72.2 C73.2 C74.2 C75.2 C76.2 C77.2 C78.2 C79.2 C80.2 C81.2 C82.2 C83.2 C84.2 C85.2 C86.2 C87.2 C88.2 C89.2 C90.2 C91.2 C92.2 C93.2 C94.2 C95.2 C96.2 C97.2 C98.2 C99.2 C100.2 C101.2 C102.2 C103.2 C104.2 C105.2 C106.2 C107.2 C108.2 C109.2 C110.2 C111.2 C112.2 C113.2 C114.2 C115.2 C116.2 C117.2 C118.2 C119.2 C120.2 C121.2 C122.2 C123.2 C124.2 C125.2 C126.2 C127.2 C128.2 C129.2 C130.2 C131.2 C132.2 C133.2 C134.2 C135.2 C136.2 C137.2 C138.2 C139.2 C140.2 C141.2 C142.2 C143.2 C144.2 C145.2 C146.2 C147.2 C148.2 C149.2 C150.2 C151.2 C152.2 C153.2 C154.2 C155.2 C156.2 C157.2 C158.2 C159.2 C160.2 C161.2 C162.2 C163.2 C164.2 C165.2 C166.2 C167.2 C168.2 C169.2 C170.2 C171.2 C172.2 C173.2 C174.2 C175.2 C176.2 C177.2 C178.2 C179.2 C180.2 C181.2 C182.2 C183.2 C184.2 C185.2 C186.2 C187.2 C188.2 C189.2 C190.2 C191.2 C192.2 C193.2 C194.2 C195.2 C196.2 C197.2 C198.2 C199.2 C200.2 C201.2 C202.2 C203.2 C204.2 C205.2 C206.2 C207.2 C208.2 C209.2 C210.2 C211.2 C212.2 C213.2 C214.2 LED1.4(VDD) LED2.4(VDD) LED3.4(VDD) LED4.4(VDD) LED5.4(VDD) LED6.4(VDD) LED7.4(VDD) LED8.4(VDD) LED9.4(VDD) LED10.4(VDD) LED11.4(VDD) LED12.4(VDD) LED13.4(VDD) LED14.4(VDD) LED15.4(VDD) LED16.4(VDD) LED17.4(VDD) LED18.4(VDD) LED19.4(VDD) LED20.4(VDD) LED21.4(VDD) LED22.4(VDD) LED23.4(VDD) LED24.4(VDD) LED25.4(VDD) LED26.4(VDD) LED27.4(VDD) LED28.4(VDD) LED29.4(VDD) LED30.4(VDD) LED31.4(VDD) LED32.4(VDD) LED33.4(VDD) LED34.4(VDD) LED35.4(VDD) LED36.4(VDD) LED37.4(VDD) LED38.4(VDD) LED39.4(VDD) LED40.4(VDD) LED41.4(VDD) LED42.4(VDD) LED43.4(VDD) LED44.4(VDD) LED45.4(VDD) LED46.4(VDD) LED47.4(VDD) LED48.4(VDD) LED49.4(VDD) LED50.4(VDD) LED51.4(VDD) LED52.4(VDD) LED53.4(VDD) LED54.4(VDD) LED55.4(VDD) LED56.4(VDD) LED57.4(VDD) LED58.4(VDD) LED59.4(VDD) LED60.4(VDD) LED61.4(VDD) LED62.4(VDD) LED63.4(VDD) LED64.4(VDD) LED65.4(VDD) LED66.4(VDD) LED67.4(VDD) LED68.4(VDD) LED69.4(VDD) LED70.4(VDD) LED71.4(VDD) LED72.4(VDD) LED73.4(VDD) LED74.4(VDD) LED75.4(VDD) LED76.4(VDD) LED77.4(VDD) LED78.4(VDD) LED79.4(VDD) LED80.4(VDD) LED81.4(VDD) LED82.4(VDD) LED83.4(VDD) LED84.4(VDD) LED85.4(VDD) LED86.4(VDD) LED87.4(VDD) LED88.4(VDD) LED89.4(VDD) LED90.4(VDD) LED91.4(VDD) LED92.4(VDD) LED93.4(VDD) LED94.4(VDD) LED95.4(VDD) LED96.4(VDD) LED97.4(VDD) LED98.4(VDD) LED99.4(VDD) LED100.4(VDD) LED101.4(VDD) LED102.4(VDD) LED103.4(VDD) LED104.4(VDD) LED105.4(VDD) LED106.4(VDD) LED107.4(VDD) LED108.4(VDD) LED109.4(VDD) LED110.4(VDD) LED111.4(VDD) LED112.4(VDD) LED113.4(VDD) LED114.4(VDD) LED115.4(VDD) LED116.4(VDD) LED117.4(VDD) LED118.4(VDD) LED119.4(VDD) LED120.4(VDD) LED121.4(VDD) LED122.4(VDD) LED123.4(VDD) LED124.4(VDD) LED125.4(VDD) LED126.4(VDD) LED127.4(VDD) LED128.4(VDD) LED129.4(VDD) LED130.4(VDD) LED131.4(VDD) LED132.4(VDD) LED133.4(VDD) LED134.4(VDD) LED135.4(VDD) LED136.4(VDD) LED137.4(VDD) LED138.4(VDD) LED139.4(VDD) LED140.4(VDD) LED141.4(VDD) LED142.4(VDD) LED143.4(VDD) LED144.4(VDD) LED145.4(VDD) LED146.4(VDD) LED147.4(VDD) LED148.4(VDD) LED149.4(VDD) LED150.4(VDD) LED151.4(VDD) LED152.4(VDD) LED153.4(VDD) LED154.4(VDD) LED155.4(VDD) LED156.4(VDD) LED157.4(VDD) LED158.4(VDD) LED159.4(VDD) LED160.4(VDD) LED161.4(VDD) LED162.4(VDD) LED163.4(VDD) LED164.4(VDD) LED165.4(VDD) LED166.4(VDD) LED167.4(VDD) LED168.4(VDD) LED169.4(VDD) LED170.4(VDD) LED171.4(VDD) LED172.4(VDD) LED173.4(VDD) LED174.4(VDD) LED175.4(VDD) LED176.4(VDD) LED177.4(VDD) LED178.4(VDD) LED179.4(VDD) LED180.4(VDD) LED181.4(VDD) LED182.4(VDD) LED183.4(VDD) LED184.4(VDD) LED185.4(VDD) LED186.4(VDD) LED187.4(VDD) LED188.4(VDD) LED189.4(VDD) LED190.4(VDD) LED191.4(VDD) LED192.4(VDD) LED193.4(VDD) LED194.4(VDD) LED195.4(VDD) LED196.4(VDD) LED197.4(VDD) LED198.4(VDD) LED199.4(VDD) LED200.4(VDD) LED201.4(VDD) LED202.4(VDD) LED203.4(VDD) LED204.4(VDD) LED205.4(VDD) LED206.4(VDD) LED207.4(VDD) LED208.4(VDD) LED209.4(VDD) LED210.4(VDD) LED211.4(VDD) LED212.4(VDD) LED213.4(VDD) LED214.4(VDD)
LEDIN: LED1.3(DI) ; port LEDIN
ROW2IN: LED25.1(DO) LED26.3(DI) ; port ROW2IN
ROW3IN: LED50.1(DO) LED51.3(DI) ; port ROW3IN
ROW4IN: LED75.1(DO) LED76.3(DI) ; port ROW4IN
ROW5IN: LED100.1(DO) LED101.3(DI) ; port ROW5IN
ROW6IN: LED125.1(DO) LED126.3(DI) ; port ROW6IN
ROW7IN: LED150.1(DO) LED151.3(DI) ; port ROW7IN
ROW8IN: LED175.1(DO) LED176.3(DI) ; port ROW8IN
ROW9IN: LED200.1(DO) LED201.3(DI) ; port ROW9IN
NetLED1_1: LED1.1(DO) LED2.3(DI)
NetLED2_1: LED2.1(DO) LED3.3(DI)
NetLED3_1: LED3.1(DO) LED4.3(DI)
NetLED4_1: LED4.1(DO) LED5.3(DI)
NetLED5_1: LED5.1(DO) LED6.3(DI)
NetLED6_1: LED6.1(DO) LED7.3(DI)
NetLED7_1: LED7.1(DO) LED8.3(DI)
NetLED8_1: LED8.1(DO) LED9.3(DI)
NetLED9_1: LED9.1(DO) LED10.3(DI)
NetLED10_1: LED10.1(DO) LED11.3(DI)
NetLED11_1: LED11.1(DO) LED12.3(DI)
NetLED12_1: LED12.1(DO) LED13.3(DI)
NetLED13_1: LED13.1(DO) LED14.3(DI)
NetLED14_1: LED14.1(DO) LED15.3(DI)
NetLED15_1: LED15.1(DO) LED16.3(DI)
NetLED16_1: LED16.1(DO) LED17.3(DI)
NetLED17_1: LED17.1(DO) LED18.3(DI)
NetLED18_1: LED18.1(DO) LED19.3(DI)
NetLED19_1: LED19.1(DO) LED20.3(DI)
NetLED20_1: LED20.1(DO) LED21.3(DI)
NetLED21_1: LED21.1(DO) LED22.3(DI)
NetLED22_1: LED22.1(DO) LED23.3(DI)
NetLED23_1: LED23.1(DO) LED24.3(DI)
NetLED24_1: LED24.1(DO) LED25.3(DI)
NetLED26_1: LED26.1(DO) LED27.3(DI)
NetLED27_1: LED27.1(DO) LED28.3(DI)
NetLED28_1: LED28.1(DO) LED29.3(DI)
NetLED29_1: LED29.1(DO) LED30.3(DI)
NetLED30_1: LED30.1(DO) LED31.3(DI)
NetLED31_1: LED31.1(DO) LED32.3(DI)
NetLED32_1: LED32.1(DO) LED33.3(DI)
NetLED33_1: LED33.1(DO) LED34.3(DI)
NetLED34_1: LED34.1(DO) LED35.3(DI)
NetLED35_1: LED35.1(DO) LED36.3(DI)
NetLED36_1: LED36.1(DO) LED37.3(DI)
NetLED37_1: LED37.1(DO) LED38.3(DI)
NetLED38_1: LED38.1(DO) LED39.3(DI)
NetLED39_1: LED39.1(DO) LED40.3(DI)
NetLED40_1: LED40.1(DO) LED41.3(DI)
NetLED41_1: LED41.1(DO) LED42.3(DI)
NetLED42_1: LED42.1(DO) LED43.3(DI)
NetLED43_1: LED43.1(DO) LED44.3(DI)
NetLED44_1: LED44.1(DO) LED45.3(DI)
NetLED45_1: LED45.1(DO) LED46.3(DI)
NetLED46_1: LED46.1(DO) LED47.3(DI)
NetLED47_1: LED47.1(DO) LED48.3(DI)
NetLED48_1: LED48.1(DO) LED49.3(DI)
NetLED49_1: LED49.1(DO) LED50.3(DI)
NetLED51_1: LED51.1(DO) LED52.3(DI)
NetLED52_1: LED52.1(DO) LED53.3(DI)
NetLED53_1: LED53.1(DO) LED54.3(DI)
NetLED54_1: LED54.1(DO) LED55.3(DI)
NetLED55_1: LED55.1(DO) LED56.3(DI)
NetLED56_1: LED56.1(DO) LED57.3(DI)
NetLED57_1: LED57.1(DO) LED58.3(DI)
NetLED58_1: LED58.1(DO) LED59.3(DI)
NetLED59_1: LED59.1(DO) LED60.3(DI)
NetLED60_1: LED60.1(DO) LED61.3(DI)
NetLED61_1: LED61.1(DO) LED62.3(DI)
NetLED62_1: LED62.1(DO) LED63.3(DI)
NetLED63_1: LED63.1(DO) LED64.3(DI)
NetLED64_1: LED64.1(DO) LED65.3(DI)
NetLED65_1: LED65.1(DO) LED66.3(DI)
NetLED66_1: LED66.1(DO) LED67.3(DI)
NetLED67_1: LED67.1(DO) LED68.3(DI)
NetLED68_1: LED68.1(DO) LED69.3(DI)
NetLED69_1: LED69.1(DO) LED70.3(DI)
NetLED70_1: LED70.1(DO) LED71.3(DI)
NetLED71_1: LED71.1(DO) LED72.3(DI)
NetLED72_1: LED72.1(DO) LED73.3(DI)
NetLED73_1: LED73.1(DO) LED74.3(DI)
NetLED74_1: LED74.1(DO) LED75.3(DI)
NetLED76_1: LED76.1(DO) LED77.3(DI)
NetLED77_1: LED77.1(DO) LED78.3(DI)
NetLED78_1: LED78.1(DO) LED79.3(DI)
NetLED79_1: LED79.1(DO) LED80.3(DI)
NetLED80_1: LED80.1(DO) LED81.3(DI)
NetLED81_1: LED81.1(DO) LED82.3(DI)
NetLED82_1: LED82.1(DO) LED83.3(DI)
NetLED83_1: LED83.1(DO) LED84.3(DI)
NetLED84_1: LED84.1(DO) LED85.3(DI)
NetLED85_1: LED85.1(DO) LED86.3(DI)
NetLED86_1: LED86.1(DO) LED87.3(DI)
NetLED87_1: LED87.1(DO) LED88.3(DI)
NetLED88_1: LED88.1(DO) LED89.3(DI)
NetLED89_1: LED89.1(DO) LED90.3(DI)
NetLED90_1: LED90.1(DO) LED91.3(DI)
NetLED91_1: LED91.1(DO) LED92.3(DI)
NetLED92_1: LED92.1(DO) LED93.3(DI)
NetLED93_1: LED93.1(DO) LED94.3(DI)
NetLED94_1: LED94.1(DO) LED95.3(DI)
NetLED95_1: LED95.1(DO) LED96.3(DI)
NetLED96_1: LED96.1(DO) LED97.3(DI)
NetLED97_1: LED97.1(DO) LED98.3(DI)
NetLED98_1: LED98.1(DO) LED99.3(DI)
NetLED99_1: LED99.1(DO) LED100.3(DI)
NetLED101_1: LED101.1(DO) LED102.3(DI)
NetLED102_1: LED102.1(DO) LED103.3(DI)
NetLED103_1: LED103.1(DO) LED104.3(DI)
NetLED104_1: LED104.1(DO) LED105.3(DI)
NetLED105_1: LED105.1(DO) LED106.3(DI)
NetLED106_1: LED106.1(DO) LED107.3(DI)
NetLED107_1: LED107.1(DO) LED108.3(DI)
NetLED108_1: LED108.1(DO) LED109.3(DI)
NetLED109_1: LED109.1(DO) LED110.3(DI)
NetLED110_1: LED110.1(DO) LED111.3(DI)
NetLED111_1: LED111.1(DO) LED112.3(DI)
NetLED112_1: LED112.1(DO) LED113.3(DI)
NetLED113_1: LED113.1(DO) LED114.3(DI)
NetLED114_1: LED114.1(DO) LED115.3(DI)
NetLED115_1: LED115.1(DO) LED116.3(DI)
NetLED116_1: LED116.1(DO) LED117.3(DI)
NetLED117_1: LED117.1(DO) LED118.3(DI)
NetLED118_1: LED118.1(DO) LED119.3(DI)
NetLED119_1: LED119.1(DO) LED120.3(DI)
NetLED120_1: LED120.1(DO) LED121.3(DI)
NetLED121_1: LED121.1(DO) LED122.3(DI)
NetLED122_1: LED122.1(DO) LED123.3(DI)
NetLED123_1: LED123.1(DO) LED124.3(DI)
NetLED124_1: LED124.1(DO) LED125.3(DI)
NetLED126_1: LED126.1(DO) LED127.3(DI)
NetLED127_1: LED127.1(DO) LED128.3(DI)
NetLED128_1: LED128.1(DO) LED129.3(DI)
NetLED129_1: LED129.1(DO) LED130.3(DI)
NetLED130_1: LED130.1(DO) LED131.3(DI)
NetLED131_1: LED131.1(DO) LED132.3(DI)
NetLED132_1: LED132.1(DO) LED133.3(DI)
NetLED133_1: LED133.1(DO) LED134.3(DI)
NetLED134_1: LED134.1(DO) LED135.3(DI)
NetLED135_1: LED135.1(DO) LED136.3(DI)
NetLED136_1: LED136.1(DO) LED137.3(DI)
NetLED137_1: LED137.1(DO) LED138.3(DI)
NetLED138_1: LED138.1(DO) LED139.3(DI)
NetLED139_1: LED139.1(DO) LED140.3(DI)
NetLED140_1: LED140.1(DO) LED141.3(DI)
NetLED141_1: LED141.1(DO) LED142.3(DI)
NetLED142_1: LED142.1(DO) LED143.3(DI)
NetLED143_1: LED143.1(DO) LED144.3(DI)
NetLED144_1: LED144.1(DO) LED145.3(DI)
NetLED145_1: LED145.1(DO) LED146.3(DI)
NetLED146_1: LED146.1(DO) LED147.3(DI)
NetLED147_1: LED147.1(DO) LED148.3(DI)
NetLED148_1: LED148.1(DO) LED149.3(DI)
NetLED149_1: LED149.1(DO) LED150.3(DI)
NetLED151_1: LED151.1(DO) LED152.3(DI)
NetLED152_1: LED152.1(DO) LED153.3(DI)
NetLED153_1: LED153.1(DO) LED154.3(DI)
NetLED154_1: LED154.1(DO) LED155.3(DI)
NetLED155_1: LED155.1(DO) LED156.3(DI)
NetLED156_1: LED156.1(DO) LED157.3(DI)
NetLED157_1: LED157.1(DO) LED158.3(DI)
NetLED158_1: LED158.1(DO) LED159.3(DI)
NetLED159_1: LED159.1(DO) LED160.3(DI)
NetLED160_1: LED160.1(DO) LED161.3(DI)
NetLED161_1: LED161.1(DO) LED162.3(DI)
NetLED162_1: LED162.1(DO) LED163.3(DI)
NetLED163_1: LED163.1(DO) LED164.3(DI)
NetLED164_1: LED164.1(DO) LED165.3(DI)
NetLED165_1: LED165.1(DO) LED166.3(DI)
NetLED166_1: LED166.1(DO) LED167.3(DI)
NetLED167_1: LED167.1(DO) LED168.3(DI)
NetLED168_1: LED168.1(DO) LED169.3(DI)
NetLED169_1: LED169.1(DO) LED170.3(DI)
NetLED170_1: LED170.1(DO) LED171.3(DI)
NetLED171_1: LED171.1(DO) LED172.3(DI)
NetLED172_1: LED172.1(DO) LED173.3(DI)
NetLED173_1: LED173.1(DO) LED174.3(DI)
NetLED174_1: LED174.1(DO) LED175.3(DI)
NetLED176_1: LED176.1(DO) LED177.3(DI)
NetLED177_1: LED177.1(DO) LED178.3(DI)
NetLED178_1: LED178.1(DO) LED179.3(DI)
NetLED179_1: LED179.1(DO) LED180.3(DI)
NetLED180_1: LED180.1(DO) LED181.3(DI)
NetLED181_1: LED181.1(DO) LED182.3(DI)
NetLED182_1: LED182.1(DO) LED183.3(DI)
NetLED183_1: LED183.1(DO) LED184.3(DI)
NetLED184_1: LED184.1(DO) LED185.3(DI)
NetLED185_1: LED185.1(DO) LED186.3(DI)
NetLED186_1: LED186.1(DO) LED187.3(DI)
NetLED187_1: LED187.1(DO) LED188.3(DI)
NetLED188_1: LED188.1(DO) LED189.3(DI)
NetLED189_1: LED189.1(DO) LED190.3(DI)
NetLED190_1: LED190.1(DO) LED191.3(DI)
NetLED191_1: LED191.1(DO) LED192.3(DI)
NetLED192_1: LED192.1(DO) LED193.3(DI)
NetLED193_1: LED193.1(DO) LED194.3(DI)
NetLED194_1: LED194.1(DO) LED195.3(DI)
NetLED195_1: LED195.1(DO) LED196.3(DI)
NetLED196_1: LED196.1(DO) LED197.3(DI)
NetLED197_1: LED197.1(DO) LED198.3(DI)
NetLED198_1: LED198.1(DO) LED199.3(DI)
NetLED199_1: LED199.1(DO) LED200.3(DI)
NetLED201_1: LED201.1(DO) LED202.3(DI)
NetLED202_1: LED202.1(DO) LED203.3(DI)
NetLED203_1: LED203.1(DO) LED204.3(DI)
NetLED204_1: LED204.1(DO) LED205.3(DI)
NetLED205_1: LED205.1(DO) LED206.3(DI)
NetLED206_1: LED206.1(DO) LED207.3(DI)
NetLED207_1: LED207.1(DO) LED208.3(DI)
NetLED208_1: LED208.1(DO) LED209.3(DI)
NetLED209_1: LED209.1(DO) LED210.3(DI)
NetLED210_1: LED210.1(DO) LED211.3(DI)
NetLED211_1: LED211.1(DO) LED212.3(DI)
NetLED212_1: LED212.1(DO) LED213.3(DI)
NetLED213_1: LED213.1(DO) LED214.3(DI)

Not connected (* = marked no-connect by the designer): LED214 1(DO)

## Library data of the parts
C1-C214 = CC0402KRX7R5BB104: Manufacturer: YAGEO(国巨); Add into BOM: yes; Tolerance: ±10%; Description: Capacitance: Tolerance:±10% Tolerance:±10% Voltage Rated: Temperature Coefficient:
LED1-LED214 = WS2812C-2020-V1: Manufacturer: worldsemi; Add into BOM: yes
